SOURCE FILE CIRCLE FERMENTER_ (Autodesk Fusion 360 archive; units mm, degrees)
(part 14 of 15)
sketch "Schizzo16" plane through (0, 0, 68.1854) normal (0, 0, 1) x axis (-1, 0, 0)
  line L1 (6.7534, -5.4136) -> (35.6534, -5.4136)
  line L2 (6.7534, -27.4136) -> (6.7534, -5.4136)
  line L3 (79.5534, -27.4136) -> (6.7534, -27.4136)
  line L4 (79.5534, -5.4136) -> (79.5534, -27.4136)
  line L5 (50.6534, -5.4136) -> (79.5534, -5.4136)
  line L6 (50.6534, -6.4136) -> (50.6534, -5.4136)
  line L7 (36.6534, -7.4136) -> (49.6534, -7.4136)
  line L8 (35.6534, -5.4136) -> (35.6534, -6.4136)
  arc A1 centre (49.6534, -6.4136) radius 1 clockwise from (50.6534, -6.4136) to (49.6534, -7.4136)
  arc A2 centre (36.6534, -6.4136) radius 1 clockwise from (36.6534, -7.4136) to (35.6534, -6.4136)
  circle C1 centre (43.1534, -7.4136) radius 1
  point P14 (43.1534, -7.4136)
  midpoint L7 P14
  dimension "d98" diameter C1 = 2
extrude "Estrusione17" cut sketch "Schizzo16" profile of L7 C1 against normal blind 15.378
sketch "Schizzo18" plane through (0, 0, -22.6146) normal (0, 0, -1) x axis (1, 0, 0)
  line L1 (-79.5534, -5.4136) -> (-6.7534, -5.4136)
  line L2 (-79.5534, -27.4136) -> (-79.5534, -5.4136)
  line L3 (-6.7534, -27.4136) -> (-79.5534, -27.4136)
  line L4 (-6.7534, -5.4136) -> (-6.7534, -27.4136)
  line L5 (-43.1534, -27.4136) -> (-43.1534, -5.4136)
  line L6 (-40.1534, -7.4136) -> (-46.1534, -7.4136)
  line L7 (-46.1534, -3.4136) -> (-40.1534, -3.4136)
  line L8 (-40.1534, -5.4136) -> (-46.1534, -5.4136)
  arc A1 centre (-40.1534, -5.4136) radius 2 clockwise from (-40.1534, -3.4136) to (-40.1534, -7.4136)
  arc A2 centre (-46.1534, -5.4136) radius 2 clockwise from (-46.1534, -7.4136) to (-46.1534, -3.4136)
  point P6 (-43.1534, -5.4136)
  point P7 (-43.1534, -27.4136)
  point P14 (-43.1534, -5.4136)
  point P13 (-40.1534, -5.4136)
  midpoint L1 P6
  midpoint L3 P7
  tangent L6 A1
  tangent A1 L7
  parallel L6 L7
  tangent L7 A2
  tangent L6 A2
  perpendicular L5 L8
  coincident P6 P14
  midpoint L8 P14
  dimension "d101" diameter A1 = 4
  dimension "d104" distance P13 P14 = 3
extrude "Estrusione18" cut sketch "Schizzo18" profile of L1 L6 A1 L7 A2 against normal blind 17.359
sketch "Schizzo19" plane through (0, 5.4136, 0) normal (0, 1, 0) x axis (-1, 0, 0)
  line L1 (48.1534, -22.6146) -> (48.1534, -20.2146)
  line L2 (79.5534, -22.6146) -> (48.1534, -22.6146)
  line L3 (85.5534, 62.1854) -> (85.5534, -16.6146)
  line L4 (50.6534, 68.1854) -> (79.5534, 68.1854)
  line L5 (50.6534, 65.7854) -> (50.6534, 68.1854)
  line L6 (71.1534, 65.7854) -> (50.6534, 65.7854)
  line L7 (83.1534, -16.2146) -> (83.1534, 53.7854)
  line L8 (48.1534, -20.2146) -> (79.1534, -20.2146)
  line L9 (38.1534, -20.2146) -> (38.1534, -22.6146)
  line L10 (7.1534, -20.2146) -> (38.1534, -20.2146)
  line L11 (3.1534, 53.7854) -> (3.1534, -16.2146)
  line L12 (35.6534, 65.7854) -> (15.1534, 65.7854)
  line L13 (35.6534, 68.1854) -> (35.6534, 65.7854)
  line L14 (6.7534, 68.1854) -> (35.6534, 68.1854)
  line L15 (0.7534, -16.6146) -> (0.7534, 62.1854)
  line L16 (38.1534, -22.6146) -> (6.7534, -22.6146)
  line L17 (79.5534, -21.4146) -> (48.1534, -21.4146)
  line L18 (84.3534, 62.1854) -> (84.3534, -16.6146)
  line L19 (50.6534, 66.9854) -> (79.5534, 66.9854)
  line L20 (6.7534, 66.9854) -> (35.6534, 66.9854)
  line L21 (1.9534, -16.6146) -> (1.9534, 62.1854)
  line L22 (38.1534, -21.4146) -> (6.7534, -21.4146)
  arc A1 centre (79.5534, -16.6146) radius 6 clockwise from (85.5534, -16.6146) to (79.5534, -22.6146)
  arc A2 centre (79.5534, 62.1854) radius 6 clockwise from (79.5534, 68.1854) to (85.5534, 62.1854)
  arc A3 centre (71.1534, 61.7854) radius 4 clockwise from (71.1534, 65.7854) to (75.1534, 61.7854)
  arc A4 centre (79.1534, 61.7854) radius 4 clockwise from (79.1534, 57.7854) to (75.1534, 61.7854)
  arc A5 centre (79.1534, 53.7854) radius 4 clockwise from (79.1534, 57.7854) to (83.1534, 53.7854)
  arc A6 centre (79.1534, -16.2146) radius 4 clockwise from (83.1534, -16.2146) to (79.1534, -20.2146)
  circle C1 centre (79.1534, 61.7854) radius 1.875
  arc A7 centre (7.1534, -16.2146) radius 4 clockwise from (7.1534, -20.2146) to (3.1534, -16.2146)
  arc A8 centre (7.1534, 53.7854) radius 4 clockwise from (3.1534, 53.7854) to (7.1534, 57.7854)
  arc A9 centre (7.1534, 61.7854) radius 4 clockwise from (11.1534, 61.7854) to (7.1534, 57.7854)
  arc A10 centre (15.1534, 61.7854) radius 4 clockwise from (11.1534, 61.7854) to (15.1534, 65.7854)
  arc A11 centre (6.7534, 62.1854) radius 6 clockwise from (0.7534, 62.1854) to (6.7534, 68.1854)
  arc A12 centre (6.7534, -16.6146) radius 6 clockwise from (6.7534, -22.6146) to (0.7534, -16.6146)
  circle C2 centre (7.1534, 61.7854) radius 1.875
  arc A13 centre (79.5534, -16.6146) radius 4.8 clockwise from (84.3534, -16.6146) to (79.5534, -21.4146)
  arc A14 centre (79.5534, 62.1854) radius 4.8 clockwise from (79.5534, 66.9854) to (84.3534, 62.1854)
  arc A15 centre (6.7534, 62.1854) radius 4.8 clockwise from (1.9534, 62.1854) to (6.7534, 66.9854)
  arc A16 centre (6.7534, -16.6146) radius 4.8 clockwise from (6.7534, -21.4146) to (1.9534, -16.6146)
  dimension "d105" = -1.2
  dimension "d106" = -1.2
extrude "Estrusione19" cut sketch "Schizzo19" profile of L1 L2 A1 L3 A2 L4 L5 L9 L13 L14 A11 L15 A12 L16 A13 L17 L18 A14 L19 L20 L21 A15 A16 L22 against normal blind 1
extrude "Estrusione20" cut of existing geometry blind -13.899
sketch "Schizzo20" plane through (0, 5.4136, 0) normal (0, -1, 0) x axis (1, 0, 0)
  line L1 (-48.1534, -20.2146) -> (-48.1534, -22.6146)
  line L2 (-71.1534, -20.2146) -> (-48.1534, -20.2146)
  line L3 (-83.1534, 53.7854) -> (-83.1534, -8.2146)
  line L4 (-50.6534, 65.7854) -> (-71.1534, 65.7854)
  line L5 (-50.6534, 68.1854) -> (-50.6534, 65.7854)
  line L6 (-79.5534, 68.1854) -> (-50.6534, 68.1854)
  line L7 (-85.5534, -16.6146) -> (-85.5534, 62.1854)
  line L8 (-48.1534, -22.6146) -> (-79.5534, -22.6146)
  line L9 (-38.1534, -22.6146) -> (-38.1534, -20.2146)
  line L10 (-6.7534, -22.6146) -> (-38.1534, -22.6146)
  line L11 (-0.7534, 62.1854) -> (-0.7534, -16.6146)
  line L12 (-35.6534, 68.1854) -> (-6.7534, 68.1854)
  line L13 (-35.6534, 65.7854) -> (-35.6534, 68.1854)
  line L14 (-15.1534, 65.7854) -> (-35.6534, 65.7854)
  line L15 (-3.1534, -8.2146) -> (-3.1534, 53.7854)
  line L16 (-38.1534, -20.2146) -> (-15.1534, -20.2146)
  line L17 (-79.5534, 67.3854) -> (-50.6534, 67.3854)
  line L18 (-84.7534, -16.6146) -> (-84.7534, 62.1854)
  line L19 (-48.1534, -21.8146) -> (-79.5534, -21.8146)
  line L20 (-6.7534, -21.8146) -> (-38.1534, -21.8146)
  line L21 (-1.5534, 62.1854) -> (-1.5534, -16.6146)
  line L22 (-35.6534, 67.3854) -> (-6.7534, 67.3854)
  arc A1 centre (-71.1534, -16.2146) radius 4 clockwise from (-71.1534, -20.2146) to (-75.1534, -16.2146)
  arc A2 centre (-79.1534, -16.2146) radius 4 clockwise from (-79.1534, -12.2146) to (-75.1534, -16.2146)
  arc A3 centre (-79.1534, -8.2146) radius 4 clockwise from (-79.1534, -12.2146) to (-83.1534, -8.2146)
  arc A4 centre (-79.1534, 53.7854) radius 4 clockwise from (-83.1534, 53.7854) to (-79.1534, 57.7854)
  arc A5 centre (-79.1534, 61.7854) radius 4 clockwise from (-75.1534, 61.7854) to (-79.1534, 57.7854)
  arc A6 centre (-71.1534, 61.7854) radius 4 clockwise from (-75.1534, 61.7854) to (-71.1534, 65.7854)
  arc A7 centre (-79.5534, 62.1854) radius 6 clockwise from (-85.5534, 62.1854) to (-79.5534, 68.1854)
  arc A8 centre (-79.5534, -16.6146) radius 6 clockwise from (-79.5534, -22.6146) to (-85.5534, -16.6146)
  circle C1 centre (-79.1534, -16.2146) radius 1.725
  circle C2 centre (-79.1534, 61.7854) radius 1.875
  circle C3 centre (-7.1534, -16.2146) radius 1.725
  circle C4 centre (-7.1534, 61.7854) radius 1.875
  arc A9 centre (-6.7534, -16.6146) radius 6 clockwise from (-0.7534, -16.6146) to (-6.7534, -22.6146)
  arc A10 centre (-6.7534, 62.1854) radius 6 clockwise from (-6.7534, 68.1854) to (-0.7534, 62.1854)
  arc A11 centre (-15.1534, 61.7854) radius 4 clockwise from (-15.1534, 65.7854) to (-11.1534, 61.7854)
  arc A12 centre (-7.1534, 61.7854) radius 4 clockwise from (-7.1534, 57.7854) to (-11.1534, 61.7854)
  arc A13 centre (-7.1534, 53.7854) radius 4 clockwise from (-7.1534, 57.7854) to (-3.1534, 53.7854)
  arc A14 centre (-7.1534, -8.2146) radius 4 clockwise from (-3.1534, -8.2146) to (-7.1534, -12.2146)
  arc A15 centre (-7.1534, -16.2146) radius 4 clockwise from (-11.1534, -16.2146) to (-7.1534, -12.2146)
  arc A16 centre (-15.1534, -16.2146) radius 4 clockwise from (-11.1534, -16.2146) to (-15.1534, -20.2146)
  arc A17 centre (-79.5534, 62.1854) radius 5.2 clockwise from (-84.7534, 62.1854) to (-79.5534, 67.3854)
  arc A18 centre (-79.5534, -16.6146) radius 5.2 clockwise from (-79.5534, -21.8146) to (-84.7534, -16.6146)
  arc A19 centre (-6.7534, -16.6146) radius 5.2 clockwise from (-1.5534, -16.6146) to (-6.7534, -21.8146)
  arc A20 centre (-6.7534, 62.1854) radius 5.2 clockwise from (-6.7534, 67.3854) to (-1.5534, 62.1854)
  dimension "d111" = -0.8
  dimension "d112" = -0.8
extrude "Estrusione21" add sketch "Schizzo20" profile of L1 L5 L6 A7 L7 A8 L8 L9 L10 A9 L11 A10 L12 L13 L19 L17 A17 L18 A18 L20 A19 L21 A20 L22 along normal blind 0.8
thread "Filettatura"
sketch "Schizzo21" plane through (0, 5.4136, 0) normal (0, -1, 0) x axis (1, 0, 0)
  curve K1 (-6.1953, 60.9602) -> (-6.7549, 63.2761)
  curve K2 (-7.5519, 63.2761) -> (-8.1115, 60.9602)
  curve K3 (-8.1115, -15.3893) -> (-7.5519, -17.7052)
  curve K4 (-6.7549, -17.7052) -> (-6.1953, -15.3893)
  line L1 (-35.6534, 67.3854) -> (-6.7534, 67.3854)
  line L2 (-35.6534, 65.7854) -> (-35.6534, 67.3854)
  line L3 (-15.1534, 65.7854) -> (-35.6534, 65.7854)
  line L4 (-3.1534, -8.2146) -> (-3.1534, 53.7854)
  line L5 (-38.1534, -20.2146) -> (-15.1534, -20.2146)
  line L6 (-38.1534, -21.8146) -> (-38.1534, -20.2146)
  line L7 (-6.7534, -21.8146) -> (-38.1534, -21.8146)
  line L8 (-1.5534, 62.1854) -> (-1.5534, -16.6146)
  curve K5 (-78.1953, 60.9602) -> (-78.7549, 63.2761)
  curve K6 (-79.5519, 63.2761) -> (-80.1115, 60.9602)
  curve K7 (-80.1115, -15.3893) -> (-79.5519, -17.7052)
  curve K8 (-78.7549, -17.7052) -> (-78.1953, -15.3893)
  line L9 (-48.1534, -21.8146) -> (-79.5534, -21.8146)
  line L10 (-48.1534, -20.2146) -> (-48.1534, -21.8146)
  line L11 (-71.1534, -20.2146) -> (-48.1534, -20.2146)
  line L12 (-83.1534, 53.7854) -> (-83.1534, -8.2146)
  line L13 (-50.6534, 65.7854) -> (-71.1534, 65.7854)
  line L14 (-50.6534, 67.3854) -> (-50.6534, 65.7854)
  line L15 (-79.5534, 67.3854) -> (-50.6534, 67.3854)
  line L16 (-84.7534, -16.6146) -> (-84.7534, 62.1854)
  line L17 (-36.6534, 72.7854) -> (-36.6534, 62.7854)
  line L18 (-49.6534, 72.7854) -> (-36.6534, 72.7854)
  line L19 (-49.6534, 62.7854) -> (-49.6534, 72.7854)
  line L20 (-36.6534, 62.7854) -> (-49.6534, 62.7854)
  line L21 (-43.1534, 62.7854) -> (-43.1534, 72.7854)
  line L22 (-35.6534, 72.7854) -> (-36.6534, 72.7854)
  line L23 (-36.6534, 62.7854) -> (-36.6534, 72.7854)
  line L24 (-36.6534, 62.7854) -> (-35.6534, 62.7854)
  line L25 (-35.6534, 72.7854) -> (-35.6534, 62.7854)
  line L26 (-35.6534, 64.2854) -> (-30.6534, 65.7854)
  line L27 (-50.6534, 64.2854) -> (-55.6534, 65.7854)
  line L28 (-50.6534, 65.7854) -> (-50.6534, 64.2854)
  arc A1 centre (-7.1534, 61.7854) radius 1.2645 clockwise from (-6.1953, 60.9602) to (-8.1115, 60.9602)
  arc A2 centre (-7.1534, 61.7854) radius 1.543 clockwise from (-7.5519, 63.2761) to (-6.7549, 63.2761)
  arc A3 centre (-7.1534, -16.2146) radius 1.2645 clockwise from (-8.1115, -15.3893) to (-6.1953, -15.3893)
  arc A4 centre (-7.1534, -16.2146) radius 1.543 clockwise from (-6.7549, -17.7052) to (-7.5519, -17.7052)
  arc A5 centre (-15.1534, 61.7854) radius 4 clockwise from (-15.1534, 65.7854) to (-11.1534, 61.7854)
  arc A6 centre (-7.1534, 61.7854) radius 4 clockwise from (-7.1534, 57.7854) to (-11.1534, 61.7854)
  arc A7 centre (-7.1534, 53.7854) radius 4 clockwise from (-7.1534, 57.7854) to (-3.1534, 53.7854)
  arc A8 centre (-7.1534, -8.2146) radius 4 clockwise from (-3.1534, -8.2146) to (-7.1534, -12.2146)
  arc A9 centre (-7.1534, -16.2146) radius 4 clockwise from (-11.1534, -16.2146) to (-7.1534, -12.2146)
  arc A10 centre (-15.1534, -16.2146) radius 4 clockwise from (-11.1534, -16.2146) to (-15.1534, -20.2146)
  arc A11 centre (-6.7534, -16.6146) radius 5.2 clockwise from (-1.5534, -16.6146) to (-6.7534, -21.8146)
  arc A12 centre (-6.7534, 62.1854) radius 5.2 clockwise from (-6.7534, 67.3854) to (-1.5534, 62.1854)
  arc A13 centre (-79.1534, 61.7854) radius 1.2645 clockwise from (-78.1953, 60.9602) to (-80.1115, 60.9602)
  arc A14 centre (-79.1534, 61.7854) radius 1.543 clockwise from (-79.5519, 63.2761) to (-78.7549, 63.2761)
  arc A15 centre (-79.1534, -16.2146) radius 1.2645 clockwise from (-80.1115, -15.3893) to (-78.1953, -15.3893)
  arc A16 centre (-79.1534, -16.2146) radius 1.543 clockwise from (-78.7549, -17.7052) to (-79.5519, -17.7052)
  arc A17 centre (-71.1534, -16.2146) radius 4 clockwise from (-71.1534, -20.2146) to (-75.1534, -16.2146)
  arc A18 centre (-79.1534, -16.2146) radius 4 clockwise from (-79.1534, -12.2146) to (-75.1534, -16.2146)
  arc A19 centre (-79.1534, -8.2146) radius 4 clockwise from (-79.1534, -12.2146) to (-83.1534, -8.2146)
  arc A20 centre (-79.1534, 53.7854) radius 4 clockwise from (-83.1534, 53.7854) to (-79.1534, 57.7854)
  arc A21 centre (-79.1534, 61.7854) radius 4 clockwise from (-75.1534, 61.7854) to (-79.1534, 57.7854)
  arc A22 centre (-71.1534, 61.7854) radius 4 clockwise from (-75.1534, 61.7854) to (-71.1534, 65.7854)
  arc A23 centre (-79.5534, 62.1854) radius 5.2 clockwise from (-84.7534, 62.1854) to (-79.5534, 67.3854)
  arc A24 centre (-79.5534, -16.6146) radius 5.2 clockwise from (-79.5534, -21.8146) to (-84.7534, -16.6146)
  point P70 (-43.1534, 72.7854)
  point P71 (-43.1534, 62.7854)
  point P76 (-30.6534, 65.7854)
  point P77 (-35.6534, 64.2854)
  point P78 (-55.6534, 65.7854)
  point P79 (-50.6534, 64.2854)
  point P59 (-50.6534, 65.7854)
  point P80 (-50.6534, 65.7854)
  point P14 (-35.6534, 65.7854)
  midpoint L18 P70
  midpoint L20 P71
  coincident L3 P76
  coincident L25 P77
  symmetric L21 P76 P78
  symmetric L21 P77 P79
  coincident P59 P80
  dimension "d115" distance P14 P77 = 1.5
  dimension "d116" distance P14 P76 = 5
extrude "Estrusione22" add sketch "Schizzo21" profile of L3 L13 L25 L26 L27 L28 against normal blind 13.536
extrude "Estrusione23" cut of existing geometry blind -18.757
extrude "Estrusione24" add sketch "Schizzo21" profile of L3 L13 L25 L26 L27 L28 along normal blind 11
fillet "Raccordo6" radius 0.5 5
fillet "Raccordo7" radius 5 0.5
component_from_bodies "Corpo->Comp2"
component_from_bodies "Corpo->Comp3"
joint "Assembla5" alignAngle 90 alignOffsetX 0 alignOffsetY 0 alignOffsetZ 0
joint "Assembla6" alignAngle 0 alignOffsetX 0 alignOffsetY 0.2 alignOffsetZ 0
work_plane "Piano di lavoro1" AlongDistance -42.4 (= "( -84.8 / 2 ) * 1 mm")
work_plane "Piano di lavoro2" AlongDistance 20
work_plane "Piano di lavoro3" AlongDistance -20
remove_instance "RimuoviIstanza"
split "Dividi1"
split "Dividi2"
remove_body "RimuoviCorpo1"
remove_body "RimuoviCorpo2"
split "Dividi3"
remove_body "RimuoviCorpo3"
remove_body "RimuoviCorpo4"
move "Sposta1"
combine "Combina1"
work_plane "Piano di lavoro1" AlongDistance -10
work_plane "Piano di lavoro2" AlongDistance -30
split "Dividi1"
remove_body "RimuoviCorpo1"
split "Dividi2"
remove_body "RimuoviCorpo2"
move "Sposta1"
combine "Combina1"
mirror "Specchio" mirrorStitchTolerance 0.1
joint "Assembla7" alignAngle -90 alignOffsetX 0 alignOffsetY 0 alignOffsetZ 0
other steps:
base_feature "Lavorazione di base1"
base_feature "Lavorazione di base1"
joint_origin "OrigineGiunto1"
create_component "CreaComponente2"
remove_body "RimuoviCorpo2"
create_component "CreaComponente3"
remove_body "RimuoviCorpo3"
joint_origin "OrigineGiunto1"
joint_origin "OrigineGiunto1"
joint_origin "OrigineGiunto2"
create_component "CreaComponente4"
joint_origin "OrigineGiunto2"

design "rotary+encoder_14mm_hole_spc"
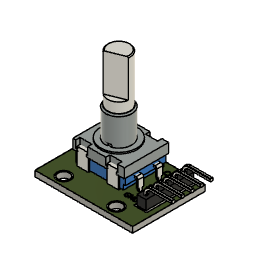
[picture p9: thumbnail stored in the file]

design "MODULO RISCALDATORE" references "PTC", "40x40x10 DC Fan"
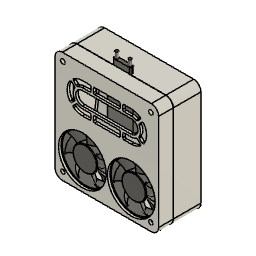
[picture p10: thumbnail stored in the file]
sketch "Schizzo1" plane through (0, 0, 0) normal (0, 1, 0) x axis (1, 0, 0)
  line L1 (40, -20) -> (-40, -20)
  line L2 (40, 20) -> (40, -20)
  line L3 (-40, 20) -> (40, 20)
  line L4 (-40, -20) -> (-40, 20)
  line L5 (40, 20) -> (-40, -20)
  line L6 (-40, 20) -> (40, -20)
  point P6 (0, 0)
  point P1 (0, 0)
  horizontal L1
  perpendicular L1 L2
  parallel L1 L3
  parallel L2 L4
  coincident L5 P6
  coincident L6 P6
  coincident P1 P6
  dimension "d1" distance L2 L4 = 80
  dimension "d2" distance L1 L3 = 40
component_insert "Inserimento componente1"
component_insert "Inserimento componente2"
joint "Assembla3" alignAngle 0 alignOffsetX 0 alignOffsetY 0 alignOffsetZ 0
sketch "Schizzo3" plane through (0, -5.5864, 0) normal (0, -1, 0) x axis (1, 0, 0)
  line L1 (-79.1534, 19.7854) -> (-47.1534, 19.7854)
  line L2 (-83.1534, -16.2146) -> (-83.1534, 15.7854)
  line L3 (-47.1534, -20.2146) -> (-79.1534, -20.2146)
  line L4 (-43.1534, 15.7854) -> (-43.1534, -16.2146)
  line L5 (-39.1534, 19.7854) -> (-7.1534, 19.7854)
  line L6 (-43.1534, -16.2146) -> (-43.1534, 15.7854)
  line L7 (-7.1534, -20.2146) -> (-39.1534, -20.2146)
  line L8 (-3.1534, 15.7854) -> (-3.1534, -16.2146)
  line L9 (-47.1534, 19.7854) -> (-39.1534, 19.7854)
  line L10 (-47.1534, -20.2146) -> (-39.1534, -20.2146)
  line L11 (-85.1534, -16.2146) -> (-85.1534, 15.7854)
  line L12 (-47.1534, -22.2146) -> (-79.1534, -22.2146)
  line L13 (-47.1534, -22.2146) -> (-39.1534, -22.2146)
  line L14 (-7.1534, -22.2146) -> (-39.1534, -22.2146)
  line L15 (-1.1534, 15.7854) -> (-1.1534, -16.2146)
  line L16 (-39.1534, 21.7854) -> (-7.1534, 21.7854)
  line L17 (-47.1534, 21.7854) -> (-39.1534, 21.7854)
  line L18 (-79.1534, 21.7854) -> (-47.1534, 21.7854)
  line L19 (-1.1534, 67.7854) -> (-1.1534, 15.7854)
  line L20 (-85.1534, 67.7854) -> (-1.1534, 67.7854)
  line L21 (-85.1534, 15.7854) -> (-85.1534, 67.7854)
  arc A1 centre (-47.1534, 15.7854) radius 4 clockwise from (-47.1534, 19.7854) to (-43.1534, 15.7854)
  arc A2 centre (-79.1534, 15.7854) radius 4 clockwise from (-83.1534, 15.7854) to (-79.1534, 19.7854)
  arc A3 centre (-79.1534, -16.2146) radius 4 clockwise from (-79.1534, -20.2146) to (-83.1534, -16.2146)
  arc A4 centre (-47.1534, -16.2146) radius 4 clockwise from (-43.1534, -16.2146) to (-47.1534, -20.2146)
  circle C1 centre (-79.1534, 15.7854) radius 1.725
  circle C2 centre (-79.1534, -16.2146) radius 1.725
  circle C3 centre (-47.1534, -16.2146) radius 1.725
  circle C4 centre (-47.1534, 15.7854) radius 1.725
  circle C5 centre (-63.1534, -0.2146) radius 19.5
  arc A5 centre (-7.1534, 15.7854) radius 4 clockwise from (-7.1534, 19.7854) to (-3.1534, 15.7854)
  arc A6 centre (-39.1534, 15.7854) radius 4 clockwise from (-43.1534, 15.7854) to (-39.1534, 19.7854)
  arc A7 centre (-39.1534, -16.2146) radius 4 clockwise from (-39.1534, -20.2146) to (-43.1534, -16.2146)
  arc A8 centre (-7.1534, -16.2146) radius 4 clockwise from (-3.1534, -16.2146) to (-7.1534, -20.2146)
  circle C6 centre (-39.1534, 15.7854) radius 1.725
  circle C7 centre (-39.1534, -16.2146) radius 1.725
  circle C8 centre (-7.1534, -16.2146) radius 1.725
  circle C9 centre (-7.1534, 15.7854) radius 1.725
  circle C10 centre (-23.1534, -0.2146) radius 19.5
  arc A9 centre (-79.1534, -16.2146) radius 6 clockwise from (-79.1534, -22.2146) to (-85.1534, -16.2146)
  arc A10 centre (-7.1534, -16.2146) radius 6 clockwise from (-1.1534, -16.2146) to (-7.1534, -22.2146)
  point P18 (-39.1534, 19.7854)
  point P28 (-39.1534, 19.7854)
  point P3 (-47.1534, 19.7854)
  point P29 (-47.1534, 19.7854)
  point P22 (-39.1534, -20.2146)
  point P30 (-39.1534, -20.2146)
  point P11 (-47.1534, -20.2146)
  point P31 (-47.1534, -20.2146)
  coincident P18 P28
  coincident P3 P29
  coincident P22 P30
  coincident P11 P31
  concentric A3 A9
  concentric A8 A10
  tangent A9 L12
  tangent L11 A9
  tangent L14 A10
  tangent A10 L15
  parallel L15 L19
  perpendicular L19 L20
  vertical L21
  dimension "d32" distance L12 L20 = 90
extrude "Estrusione2" new body sketch "Schizzo3" profile of A1 L1 A2 L2 A3 L3 A4 L4 C1 C2 C3 C4 C5 A5 L5 A6 L6 A7 L7 A8 L8 C6 C7 C8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 along normal blind 2
fillet "Raccordo1" radius 6
sketch "Schizzo4" plane through (0, -5.5864, 0) normal (0, 1, 0) x axis (-1, 0, 0)
  line L1 (1.1534, -16.2146) -> (1.1534, 61.7854)
  line L2 (79.1534, -22.2146) -> (7.1534, -22.2146)
  line L3 (85.1534, 61.7854) -> (85.1534, -16.2146)
  line L4 (7.1534, 67.7854) -> (79.1534, 67.7854)
  line L5 (7.1534, 65.7854) -> (79.1534, 65.7854)
  line L6 (3.1534, -16.2146) -> (3.1534, 61.7854)
  line L7 (79.1534, -20.2146) -> (7.1534, -20.2146)
  line L8 (83.1534, 61.7854) -> (83.1534, -16.2146)
  circle C1 centre (7.1534, -16.2146) radius 1.725
  circle C2 centre (23.1534, -0.2146) radius 19.5
  circle C3 centre (63.1534, -0.2146) radius 19.5
  circle C4 centre (79.1534, -16.2146) radius 1.725
  arc A1 centre (7.1534, 61.7854) radius 6 clockwise from (1.1534, 61.7854) to (7.1534, 67.7854)
  arc A2 centre (7.1534, -16.2146) radius 6 clockwise from (7.1534, -22.2146) to (1.1534, -16.2146)
  arc A3 centre (79.1534, -16.2146) radius 6 clockwise from (85.1534, -16.2146) to (79.1534, -22.2146)
  arc A4 centre (79.1534, 61.7854) radius 6 clockwise from (79.1534, 67.7854) to (85.1534, 61.7854)
  arc A5 centre (7.1534, 61.7854) radius 4 clockwise from (3.1534, 61.7854) to (7.1534, 65.7854)
  arc A6 centre (7.1534, -16.2146) radius 4 clockwise from (7.1534, -20.2146) to (3.1534, -16.2146)
  arc A7 centre (79.1534, -16.2146) radius 4 clockwise from (83.1534, -16.2146) to (79.1534, -20.2146)
  arc A8 centre (79.1534, 61.7854) radius 4 clockwise from (79.1534, 65.7854) to (83.1534, 61.7854)
  dimension "d37" = -2
extrude "Estrusione3" add sketch "Schizzo4" profile of A1 L1 A2 L2 A3 L3 A4 L4 L5 A8 L7 A5 L6 A6 L8 A7 along normal blind 25
component_insert "Inserimento componente3"
joint "Assembla4" alignAngle 180 alignOffsetX 0 alignOffsetY 0 alignOffsetZ 5
sketch "Schizzo5" plane through (0, -5.5864, 0) normal (0, 1, 0) x axis (-1, 0, 0)
  line L1 (7.1534, 65.7854) -> (79.1534, 65.7854)
  line L2 (3.1534, -16.2146) -> (3.1534, 61.7854)
  line L3 (79.1534, -20.2146) -> (7.1534, -20.2146)
  line L4 (83.1534, 61.7854) -> (83.1534, -16.2146)
  line L5 (47.1534, 19.7854) -> (79.1534, 19.7854)
  line L6 (7.1534, 19.7854) -> (39.1534, 19.7854)
  arc A1 centre (7.1534, 61.7854) radius 4 clockwise from (3.1534, 61.7854) to (7.1534, 65.7854)
  arc A2 centre (7.1534, -16.2146) radius 4 clockwise from (7.1534, -20.2146) to (3.1534, -16.2146)
  arc A3 centre (79.1534, -16.2146) radius 4 clockwise from (83.1534, -16.2146) to (79.1534, -20.2146)
  arc A4 centre (79.1534, 61.7854) radius 4 clockwise from (79.1534, 65.7854) to (83.1534, 61.7854)
  circle C1 centre (7.1534, -16.2146) radius 1.725
  circle C2 centre (63.1534, -0.2146) radius 19.5
  circle C3 centre (79.1534, -16.2146) radius 1.725
  circle C4 centre (23.1534, -0.2146) radius 19.5
sketch "Schizzo6" plane through (0, 0, 67.7854) normal (0, 0, 1) x axis (-1, 0, 0)
  line L1 (7.1534, -19.4136) -> (7.1534, 7.5864)
  line L2 (79.1534, -19.4136) -> (7.1534, -19.4136)
  line L3 (79.1534, 7.5864) -> (79.1534, -19.4136)
  line L4 (7.1534, 7.5864) -> (79.1534, 7.5864)
  line L5 (49.6534, -7.4136) -> (36.6534, -7.4136)
  line L6 (50.6534, -5.4136) -> (50.6534, -6.4136)
  line L7 (36.6534, -4.4136) -> (49.6534, -4.4136)
  line L8 (35.6534, -6.4136) -> (35.6534, -5.4136)
  line L9 (50.6534, -19.4136) -> (50.6534, -6.4136)
  line L10 (35.6534, -19.4136) -> (35.6534, -6.4136)
  circle C1 centre (48.6534, -5.9136) radius 1.25
  circle C2 centre (37.6534, -5.9136) radius 1.25
  arc A1 centre (36.6534, -6.4136) radius 1 clockwise from (36.6534, -7.4136) to (35.6534, -6.4136)
  arc A2 centre (49.6534, -6.4136) radius 1 clockwise from (50.6534, -6.4136) to (49.6534, -7.4136)
  arc A3 centre (49.6534, -5.4136) radius 1 clockwise from (49.6534, -4.4136) to (50.6534, -5.4136)
  arc A4 centre (36.6534, -5.4136) radius 1 clockwise from (35.6534, -5.4136) to (36.6534, -4.4136)
  point P12 (50.6534, -6.4136)
  point P20 (50.6534, -6.4136)
  point P21 (50.6534, -19.4136)
  point P8 (35.6534, -6.4136)
  point P22 (35.6534, -6.4136)
  point P23 (35.6534, -19.4136)
  coincident P12 P20
  coincident L2 P21
  tangent A2 L9
  coincident P8 P22
  coincident L2 P23
  tangent A1 L10
extrude "Estrusione4" cut sketch "Schizzo6" profile of L2 C1 C2 A1 L5 A2 L6 A3 L7 A4 L8 L9 L10 against normal blind 5.599
extrude "Estrusione5" cut of existing geometry blind -14
sketch "Schizzo7" plane through (0, -7.5864, 0) normal (0, -1, 0) x axis (1, 0, 0)
  line L1 (-79.1534, 67.7854) -> (-7.1534, 67.7854)
  line L2 (-85.1534, -16.2146) -> (-85.1534, 61.7854)
  line L3 (-7.1534, -22.2146) -> (-79.1534, -22.2146)
  line L4 (-1.1534, 61.7854) -> (-1.1534, -16.2146)
  line L5 (-43.1534, -22.2146) -> (-43.1534, 67.7854)
  line L6 (-23.1534, 31.2854) -> (-63.1534, 31.2854)
  line L7 (-63.1534, 56.2854) -> (-23.1534, 56.2854)
  line L8 (-23.1534, 43.7854) -> (-63.1534, 43.7854)
  arc A1 centre (-7.1534, 61.7854) radius 6 clockwise from (-7.1534, 67.7854) to (-1.1534, 61.7854)
  arc A2 centre (-79.1534, 61.7854) radius 6 clockwise from (-85.1534, 61.7854) to (-79.1534, 67.7854)
  arc A3 centre (-79.1534, -16.2146) radius 6 clockwise from (-79.1534, -22.2146) to (-85.1534, -16.2146)
  arc A4 centre (-7.1534, -16.2146) radius 6 clockwise from (-1.1534, -16.2146) to (-7.1534, -22.2146)
  circle C1 centre (-7.1534, -16.2146) radius 1.725
  circle C2 centre (-63.1534, -0.2146) radius 19.5
  circle C3 centre (-79.1534, -16.2146) radius 1.725
  circle C4 centre (-23.1534, -0.2146) radius 19.5
  arc A5 centre (-23.1534, 43.7854) radius 12.5 clockwise from (-23.1534, 56.2854) to (-23.1534, 31.2854)
  arc A6 centre (-63.1534, 43.7854) radius 12.5 clockwise from (-63.1534, 31.2854) to (-63.1534, 56.2854)
  point P16 (-43.1534, 67.7854)
  point P17 (-43.1534, -22.2146)
  point P24 (-43.1534, 43.7854)
  point P23 (-23.1534, 43.7854)
  midpoint L1 P16
  midpoint L3 P17
  tangent L6 A5
  tangent A5 L7
  parallel L6 L7
  tangent L7 A6
  tangent L6 A6
  perpendicular L5 L8
  coincident L5 P24
  midpoint L8 P24
  dimension "d48" distance L6 L7 = 25
  dimension "d49" distance L5 P23 = 20
  dimension "d50" distance L1 P24 = 24
extrude "Estrusione6" cut sketch "Schizzo7" profile of L6 A5 L7 A6 against normal blind 2
sketch "Schizzo8" plane through (0, -7.5864, 0) normal (0, -1, 0) x axis (1, 0, 0)
  line L1 (-63.1534, 31.2854) -> (-23.1534, 31.2854)
  line L2 (-23.1534, 56.2854) -> (-63.1534, 56.2854)
  line L3 (-79.1534, 67.7854) -> (-7.1534, 67.7854)
  line L4 (-85.1534, -16.2146) -> (-85.1534, 61.7854)
  line L5 (-7.1534, -22.2146) -> (-79.1534, -22.2146)
  line L6 (-1.1534, 61.7854) -> (-1.1534, -16.2146)
  line L7 (-23.1534, 51.2854) -> (-63.1534, 51.2854)
  line L8 (-63.1534, 36.2854) -> (-23.1534, 36.2854)
  line L9 (-23.1534, 49.2854) -> (-63.1534, 49.2854)
  line L10 (-63.1534, 38.2854) -> (-23.1534, 38.2854)
  line L11 (-43.1534, 56.2854) -> (-43.1534, 51.2854)
  line L12 (-42.1534, 56.2854) -> (-42.1534, 51.2854)
  line L13 (-44.1534, 56.2854) -> (-44.1534, 51.2854)
  line L14 (-63.1534, 43.7854) -> (-23.1534, 43.7854)
  line L15 (-71.9922, 52.6243) -> (-63.1534, 43.7854)
  line L16 (-50.6534, 43.7854) -> (-63.1534, 43.7854)
  line L17 (-71.2568, 53.3031) -> (-67.7022, 49.7485)
  line L18 (-72.671, 51.8888) -> (-69.1164, 48.3343)
  line L19 (-54.1534, 51.2854) -> (-56.1534, 51.2854)
  line L20 (-54.1534, 56.2854) -> (-54.1534, 51.2854)
  line L21 (-56.1534, 56.2854) -> (-54.1534, 56.2854)
  line L22 (-56.1534, 51.2854) -> (-56.1534, 56.2854)
  line L23 (-15.05, 53.3031) -> (-18.6045, 49.7485)
  line L24 (-13.6358, 51.8888) -> (-17.1903, 48.3343)
  line L25 (-30.1534, 51.2854) -> (-30.1534, 56.2854)
  line L26 (-32.1534, 56.2854) -> (-32.1534, 51.2854)
  line L27 (-44.1534, 31.2854) -> (-44.1534, 36.2854)
  line L28 (-42.1534, 31.2854) -> (-42.1534, 36.2854)
  line L29 (-32.1534, 31.2854) -> (-32.1534, 36.2854)
  line L30 (-30.1534, 36.2854) -> (-30.1534, 31.2854)
  line L31 (-15.05, 34.2678) -> (-18.6045, 37.8224)
  line L32 (-13.6358, 35.682) -> (-17.1903, 39.2366)
  line L33 (-54.1534, 31.2854) -> (-54.1534, 36.2854)
  line L34 (-56.1534, 36.2854) -> (-56.1534, 31.2854)
  line L35 (-71.2568, 34.2678) -> (-67.7022, 37.8224)
  line L36 (-72.671, 35.682) -> (-69.1164, 39.2366)
  arc A1 centre (-63.1534, 43.7854) radius 12.5 clockwise from (-63.1534, 31.2854) to (-63.1534, 56.2854)
  arc A2 centre (-23.1534, 43.7854) radius 12.5 clockwise from (-23.1534, 56.2854) to (-23.1534, 31.2854)
  arc A3 centre (-7.1534, 61.7854) radius 6 clockwise from (-7.1534, 67.7854) to (-1.1534, 61.7854)
  arc A4 centre (-79.1534, 61.7854) radius 6 clockwise from (-85.1534, 61.7854) to (-79.1534, 67.7854)
  arc A5 centre (-79.1534, -16.2146) radius 6 clockwise from (-79.1534, -22.2146) to (-85.1534, -16.2146)
  arc A6 centre (-7.1534, -16.2146) radius 6 clockwise from (-1.1534, -16.2146) to (-7.1534, -22.2146)
  circle C1 centre (-7.1534, -16.2146) radius 1.725
  circle C2 centre (-63.1534, -0.2146) radius 19.5
  circle C3 centre (-79.1534, -16.2146) radius 1.725
  circle C4 centre (-23.1534, -0.2146) radius 19.5
  arc A7 centre (-23.1534, 43.7854) radius 7.5 clockwise from (-23.1534, 51.2854) to (-23.1534, 36.2854)
  arc A8 centre (-63.1534, 43.7854) radius 7.5 clockwise from (-63.1534, 36.2854) to (-63.1534, 51.2854)
  arc A9 centre (-23.1534, 43.7854) radius 5.5 clockwise from (-23.1534, 49.2854) to (-23.1534, 38.2854)
  arc A10 centre (-63.1534, 43.7854) radius 5.5 clockwise from (-63.1534, 38.2854) to (-63.1534, 49.2854)
  point P34 (-43.1534, 51.2854)
  point P35 (-43.1534, 56.2854)
  point P36 (-42.1534, 51.2854)
  point P37 (-42.1534, 56.2854)
  point P38 (-44.1534, 51.2854)
  point P39 (-44.1534, 56.2854)
  point P7 (-23.1534, 43.7854)
  point P40 (-23.1534, 43.7854)
  point P5 (-63.1534, 43.7854)
  point P41 (-63.1534, 43.7854)
  point P42 (-63.1534, 43.7854)
  point P45 (-67.7022, 49.7485)
  point P46 (-71.2568, 53.3031)
  point P47 (-69.1164, 48.3343)
  point P48 (-72.671, 51.8888)
  point P51 (-54.1534, 56.2854)
  point P49 (-56.1534, 51.2854)
  point P53 (-18.6045, 49.7485)
  point P54 (-15.05, 53.3031)
  point P55 (-17.1903, 48.3343)
  point P56 (-13.6358, 51.8888)
  point P58 (-30.1534, 51.2854)
  point P50 (-54.1534, 51.2854)
  point P59 (-32.1534, 51.2854)
  point P60 (-32.1534, 56.2854)
  point P52 (-56.1534, 56.2854)
  point P57 (-30.1534, 56.2854)
  point P63 (-42.1534, 36.2854)
  point P64 (-42.1534, 31.2854)
  point P61 (-44.1534, 36.2854)
  point P62 (-44.1534, 31.2854)
  point P77 (-67.7022, 37.8224)
  point P78 (-71.2568, 34.2678)
  point P79 (-69.1164, 39.2366)
  point P80 (-72.671, 35.682)
  point P76 (-56.1534, 36.2854)
  point P73 (-54.1534, 36.2854)
  point P74 (-54.1534, 31.2854)
  point P75 (-56.1534, 31.2854)
  point P69 (-18.6045, 37.8224)
  point P70 (-15.05, 34.2678)
  point P71 (-17.1903, 39.2366)
  point P72 (-13.6358, 35.682)
  point P67 (-30.1534, 31.2854)
  point P68 (-30.1534, 36.2854)
  point P65 (-32.1534, 36.2854)
  point P66 (-32.1534, 31.2854)
  midpoint L7 P34
  midpoint L2 P35
  perpendicular L2 L11
  coincident L7 P36
  coincident L2 P37
  perpendicular L2 L12
  coincident L7 P38
  coincident L2 P39
  perpendicular L2 L13
  coincident P7 P40
  coincident P5 P41
  horizontal L16
  coincident P5 P42
  coincident A8 P45
  coincident A1 P46
  coincident A8 P47
  coincident A1 P48
  parallel L15 L18
  parallel L15 L17
  horizontal L19
  vertical L20
  horizontal L21
  vertical L22
  coincident L2 P51
  coincident L7 P49
  symmetric L11 P45 P53
  symmetric L11 P46 P54
  symmetric L11 P47 P55
  symmetric L11 P48 P56
  symmetric L11 P49 P58
  symmetric L11 P50 P59
  symmetric L11 P51 P60
  symmetric L11 P52 P57
  symmetric P36 L14 P63
  symmetric P37 L14 P64
  symmetric P38 L14 P61
  symmetric P39 L14 P62
  symmetric L14 P45 P77
  symmetric L14 P46 P78
  symmetric L14 P47 P79
  symmetric L14 P48 P80
  symmetric L14 P49 P76
  symmetric L14 P50 P73
  symmetric L14 P51 P74
  symmetric L14 P52 P75
  symmetric L14 P53 P69
  symmetric L14 P54 P70
  symmetric L14 P55 P71
  symmetric L14 P56 P72
  symmetric L14 P57 P67
  symmetric L14 P58 P68
  symmetric L14 P59 P65
  symmetric L14 P60 P66
  dimension "d53" = -5
  dimension "d54" = -7
  dimension "d55" distance L11 L13 = 1
  dimension "d56" distance L11 L12 = 1 (= "d55")
  dimension "d57" angle L15 L16 = 135
  dimension "d58" distance L17 L18 = 2
  dimension "d59" distance L15 L17 = 1
  dimension "d60" distance L20 L22 = 2
  dimension "d61" distance L12 L20 = 12
extrude "Estrusione7" add sketch "Schizzo8" profile of L1 A1 L2 A2 L7 A7 L8 A8 L9 A9 L10 A10 L17 L18 L19 L20 L21 L22 L23 L24 L25 L26 L29 L30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 against normal blind 2
fillet "Raccordo2" radius 1
offset_faces "FacceDiOffset" distance 0.4
sketch "Schizzo9" plane through (0, -5.5864, 0) normal (0, 1, 0) x axis (-1, 0, 0)
  line L1 (57.1534, 31.2854) -> (63.1534, 31.2854)
  curve K1 (57.1534, 31.2854) -> (56.1534, 32.2854)
  line L2 (56.1534, 35.2854) -> (56.1534, 32.2854)
  curve K2 (56.1534, 35.2854) -> (57.1534, 36.2854)
  line L3 (63.1534, 36.2854) -> (57.1534, 36.2854)
  curve K3 (67.0599, 37.3832) -> (68.2879, 37.2367)
  line L4 (70.4541, 35.0705) -> (68.2879, 37.2367)
  curve K4 (70.4541, 35.0705) -> (70.3203, 33.5441)
  line L5 (33.1534, 31.2854) -> (53.1534, 31.2854)
  curve K5 (33.1534, 31.2854) -> (32.1534, 32.2854)
  line L6 (32.1534, 35.2854) -> (32.1534, 32.2854)
  curve K6 (32.1534, 35.2854) -> (33.1534, 36.2854)
  line L7 (53.1534, 36.2854) -> (33.1534, 36.2854)
  curve K7 (53.1534, 36.2854) -> (54.1534, 35.2854)
  line L8 (54.1534, 32.2854) -> (54.1534, 35.2854)
  curve K8 (54.1534, 32.2854) -> (53.1534, 31.2854)
  line L9 (23.1534, 31.2854) -> (29.1534, 31.2854)
  curve K9 (15.9864, 33.5441) -> (15.8527, 35.0705)
  line L10 (18.0188, 37.2367) -> (15.8527, 35.0705)
  curve K10 (18.0188, 37.2367) -> (19.2468, 37.3832)
  line L11 (29.1534, 36.2854) -> (23.1534, 36.2854)
  curve K11 (29.1534, 36.2854) -> (30.1534, 35.2854)
  line L12 (30.1534, 32.2854) -> (30.1534, 35.2854)
  curve K12 (30.1534, 32.2854) -> (29.1534, 31.2854)
  curve K13 (12.912, 50.9524) -> (14.4385, 51.0862)
  line L13 (16.6046, 48.92) -> (14.4385, 51.0862)
  curve K14 (16.6046, 48.92) -> (16.7511, 47.692)
  curve K15 (16.7511, 39.8789) -> (16.6046, 38.6509)
  line L14 (14.4385, 36.4847) -> (16.6046, 38.6509)
  curve K16 (14.4385, 36.4847) -> (12.912, 36.6185)
  line L15 (29.1534, 56.2854) -> (23.1534, 56.2854)
  curve K17 (29.1534, 56.2854) -> (30.1534, 55.2854)
  line L16 (30.1534, 52.2854) -> (30.1534, 55.2854)
  curve K18 (30.1534, 52.2854) -> (29.1534, 51.2854)
  line L17 (23.1534, 51.2854) -> (29.1534, 51.2854)
  curve K19 (19.2468, 50.1877) -> (18.0188, 50.3342)
  line L18 (15.8527, 52.5004) -> (18.0188, 50.3342)
  curve K20 (15.8527, 52.5004) -> (15.9864, 54.0268)
  line L19 (53.1534, 56.2854) -> (33.1534, 56.2854)
  curve K21 (53.1534, 56.2854) -> (54.1534, 55.2854)
  line L20 (54.1534, 52.2854) -> (54.1534, 55.2854)
  curve K22 (54.1534, 52.2854) -> (53.1534, 51.2854)
  line L21 (33.1534, 51.2854) -> (53.1534, 51.2854)
  curve K23 (33.1534, 51.2854) -> (32.1534, 52.2854)
  line L22 (32.1534, 55.2854) -> (32.1534, 52.2854)
  curve K24 (32.1534, 55.2854) -> (33.1534, 56.2854)
  line L23 (63.1534, 56.2854) -> (57.1534, 56.2854)
  curve K25 (70.3203, 54.0268) -> (70.4541, 52.5004)
  line L24 (68.2879, 50.3342) -> (70.4541, 52.5004)
  curve K26 (68.2879, 50.3342) -> (67.0599, 50.1877)
  line L25 (57.1534, 51.2854) -> (63.1534, 51.2854)
  curve K27 (57.1534, 51.2854) -> (56.1534, 52.2854)
  line L26 (56.1534, 55.2854) -> (56.1534, 52.2854)
  curve K28 (56.1534, 55.2854) -> (57.1534, 56.2854)
  line L27 (63.1534, 49.2854) -> (23.1534, 49.2854)
  line L28 (23.1534, 38.2854) -> (63.1534, 38.2854)
  line L29 (69.7021, 38.6509) -> (71.8683, 36.4847)
  curve K29 (69.7021, 38.6509) -> (69.5556, 39.8789)
  curve K30 (69.5556, 47.692) -> (69.7021, 48.92)
  line L30 (71.8683, 51.0862) -> (69.7021, 48.92)
  curve K31 (71.8683, 51.0862) -> (73.3947, 50.9524)
  curve K32 (73.3947, 36.6185) -> (71.8683, 36.4847)
  line L31 (7.1534, 65.7854) -> (79.1534, 65.7854)
  line L32 (3.1534, -16.2146) -> (3.1534, 61.7854)
  line L33 (79.1534, -20.2146) -> (7.1534, -20.2146)
  line L34 (83.1534, 61.7854) -> (83.1534, -16.2146)
  line L35 (3.1534, 22.7854) -> (83.1534, 22.7854)
  arc A1 centre (63.1534, 43.7854) radius 12.5 clockwise from (70.3203, 33.5441) to (63.1534, 31.2854)
  arc A2 centre (63.1534, 43.7854) radius 7.5 clockwise from (67.0599, 37.3832) to (63.1534, 36.2854)
  arc A3 centre (23.1534, 43.7854) radius 12.5 clockwise from (23.1534, 31.2854) to (15.9864, 33.5441)
  arc A4 centre (23.1534, 43.7854) radius 7.5 clockwise from (23.1534, 36.2854) to (19.2468, 37.3832)
  arc A5 centre (23.1534, 43.7854) radius 12.5 clockwise from (12.912, 36.6185) to (12.912, 50.9524)
  arc A6 centre (23.1534, 43.7854) radius 7.5 clockwise from (16.7511, 39.8789) to (16.7511, 47.692)
  arc A7 centre (23.1534, 43.7854) radius 12.5 clockwise from (15.9864, 54.0268) to (23.1534, 56.2854)
  arc A8 centre (23.1534, 43.7854) radius 7.5 clockwise from (19.2468, 50.1877) to (23.1534, 51.2854)
  arc A9 centre (63.1534, 43.7854) radius 12.5 clockwise from (63.1534, 56.2854) to (70.3203, 54.0268)
  arc A10 centre (63.1534, 43.7854) radius 7.5 clockwise from (63.1534, 51.2854) to (67.0599, 50.1877)
  arc A11 centre (23.1534, 43.7854) radius 5.5 clockwise from (23.1534, 38.2854) to (23.1534, 49.2854)
  arc A12 centre (63.1534, 43.7854) radius 5.5 clockwise from (63.1534, 49.2854) to (63.1534, 38.2854)
  arc A13 centre (63.1534, 43.7854) radius 7.5 clockwise from (69.5556, 47.692) to (69.5556, 39.8789)
  arc A14 centre (63.1534, 43.7854) radius 12.5 clockwise from (73.3947, 50.9524) to (73.3947, 36.6185)
  arc A15 centre (7.1534, 61.7854) radius 4 clockwise from (3.1534, 61.7854) to (7.1534, 65.7854)
  arc A16 centre (7.1534, -16.2146) radius 4 clockwise from (7.1534, -20.2146) to (3.1534, -16.2146)
  arc A17 centre (79.1534, -16.2146) radius 4 clockwise from (83.1534, -16.2146) to (79.1534, -20.2146)
  arc A18 centre (79.1534, 61.7854) radius 4 clockwise from (79.1534, 65.7854) to (83.1534, 61.7854)
  circle C1 centre (7.1534, -16.2146) radius 1.725
  circle C2 centre (63.1534, -0.2146) radius 19.5
  circle C3 centre (79.1534, -16.2146) radius 1.725
  circle C4 centre (23.1534, -0.2146) radius 19.5
  circle C5 centre (7.1534, -16.2146) radius 1.725
  circle C6 centre (79.1534, -16.2146) radius 1.725
  circle C7 centre (79.1534, 61.7854) radius 1.725
  circle C8 centre (7.1534, 61.7854) radius 1.875
  circle C9 centre (79.1534, 61.7854) radius 1.875
  circle C10 centre (79.1534, 61.7854) radius 4
  circle C11 centre (7.1534, 61.7854) radius 4
  point P96 (83.1534, 22.7854)
  point P97 (3.1534, 22.7854)
  point P94 (7.1534, -16.2146)
  point P98 (7.1534, 61.7854)
  midpoint L34 P96
  midpoint L32 P97
  symmetric C3 L35 C7
  symmetric P94 L35 P98
  concentric A15 C8
  concentric A18 C9
  concentric A18 C10
  concentric A15 C11
  dimension "d67" diameter C8 = 3.75
  dimension "d68" diameter C9 = 3.75
  dimension "d69" diameter C11 = 8
  dimension "d70" diameter C10 = 8
extrude "Estrusione8" add sketch "Schizzo9" profile of A15 A18 C8 C9 C10 C11 along normal blind 11
fillet "Raccordo3" radius 4
extrude "Estrusione9" new body of existing geometry blind 20
sketch "Schizzo10" plane through (0, 25.4136, 0) normal (0, 1, 0) x axis (-1, 0, 0)
  line L1 (85.5534, 62.1854) -> (85.5534, -16.6146)
  line L2 (50.6534, 68.1854) -> (79.5534, 68.1854)
  line L3 (50.6534, 65.7854) -> (50.6534, 68.1854)
  line L4 (71.1534, 65.7854) -> (50.6534, 65.7854)
  line L5 (83.1534, -16.2146) -> (83.1534, 53.7854)
  line L6 (7.1534, -20.2146) -> (79.1534, -20.2146)
  line L7 (3.1534, 53.7854) -> (3.1534, -16.2146)
  line L8 (35.6534, 65.7854) -> (15.1534, 65.7854)
  line L9 (35.6534, 68.1854) -> (35.6534, 65.7854)
  line L10 (6.7534, 68.1854) -> (35.6534, 68.1854)
  line L11 (0.7534, -16.6146) -> (0.7534, 62.1854)
  line L12 (79.5534, -22.6146) -> (6.7534, -22.6146)
  line L13 (0.7534, 22.7854) -> (85.5534, 22.7854)
  circle C1 centre (79.1534, 61.7854) radius 1.875
  circle C2 centre (7.1534, 61.7854) radius 1.875
  arc A1 centre (79.5534, -16.6146) radius 6 clockwise from (85.5534, -16.6146) to (79.5534, -22.6146)
  arc A2 centre (79.5534, 62.1854) radius 6 clockwise from (79.5534, 68.1854) to (85.5534, 62.1854)
  arc A3 centre (71.1534, 61.7854) radius 4 clockwise from (71.1534, 65.7854) to (75.1534, 61.7854)
  arc A4 centre (79.1534, 61.7854) radius 4 clockwise from (79.1534, 57.7854) to (75.1534, 61.7854)
  arc A5 centre (79.1534, 53.7854) radius 4 clockwise from (79.1534, 57.7854) to (83.1534, 53.7854)
  arc A6 centre (79.1534, -16.2146) radius 4 clockwise from (83.1534, -16.2146) to (79.1534, -20.2146)
  arc A7 centre (7.1534, -16.2146) radius 4 clockwise from (7.1534, -20.2146) to (3.1534, -16.2146)
  arc A8 centre (7.1534, 53.7854) radius 4 clockwise from (3.1534, 53.7854) to (7.1534, 57.7854)
  arc A9 centre (7.1534, 61.7854) radius 4 clockwise from (11.1534, 61.7854) to (7.1534, 57.7854)
  arc A10 centre (15.1534, 61.7854) radius 4 clockwise from (11.1534, 61.7854) to (15.1534, 65.7854)
  arc A11 centre (6.7534, 62.1854) radius 6 clockwise from (0.7534, 62.1854) to (6.7534, 68.1854)
  arc A12 centre (6.7534, -16.6146) radius 6 clockwise from (6.7534, -22.6146) to (0.7534, -16.6146)
  arc A13 centre (7.1534, -8.2146) radius 4 clockwise from (7.1534, -12.2146) to (3.1534, -8.2146)
  arc A14 centre (7.1534, -16.2146) radius 4 clockwise from (7.1534, -12.2146) to (11.1534, -16.2146)
  arc A15 centre (15.1534, -16.2146) radius 4 clockwise from (15.1534, -20.2146) to (11.1534, -16.2146)
  arc A16 centre (71.1534, -16.2146) radius 4 clockwise from (75.1534, -16.2146) to (71.1534, -20.2146)
  arc A17 centre (79.1534, -16.2146) radius 4 clockwise from (75.1534, -16.2146) to (79.1534, -12.2146)
  arc A18 centre (79.1534, -8.2146) radius 4 clockwise from (83.1534, -8.2146) to (79.1534, -12.2146)
  point P38 (85.5534, 22.7854)
  point P39 (0.7534, 22.7854)
  point P12 (71.1534, 65.7854)
  point P49 (71.1534, -20.2146)
  point P13 (75.1534, 61.7854)
  point P48 (75.1534, -16.2146)
  point P15 (79.1534, 57.7854)
  point P51 (79.1534, -12.2146)
  point P16 (83.1534, 53.7854)
  point P53 (83.1534, -8.2146)
  point P24 (3.1534, 53.7854)
  point P42 (3.1534, -8.2146)
  point P25 (7.1534, 57.7854)
  point P41 (7.1534, -12.2146)
  point P27 (11.1534, 61.7854)
  point P44 (11.1534, -16.2146)
  point P28 (15.1534, 65.7854)
  point P46 (15.1534, -20.2146)
  midpoint L1 P38
  midpoint L11 P39
  symmetric P12 L13 P49
  symmetric P13 L13 P48
  symmetric A3 L13 A16
  symmetric P15 L13 P51
  symmetric A4 L13 A17
  symmetric P16 L13 P53
  symmetric A5 L13 A18
  symmetric P24 L13 P42
  symmetric P25 L13 P41
  symmetric A8 L13 A13
  symmetric P27 L13 P44
  symmetric A9 L13 A14
  symmetric P28 L13 P46
  symmetric A10 L13 A15
extrude "Estrusione10" add sketch "Schizzo10" profile of L5 A6 L6 A7 L7 A13 A14 A15 A16 A17 A18 against normal blind 20
extrude "Estrusione11" cut of existing geometry blind -11.284
sketch "Schizzo11" plane through (0, 25.4136, 0) normal (0, 1, 0) x axis (-1, 0, 0)
  line L1 (85.5534, 62.1854) -> (85.5534, -16.6146)
  line L2 (50.6534, 68.1854) -> (79.5534, 68.1854)
  line L3 (50.6534, 65.7854) -> (50.6534, 68.1854)
  line L4 (71.1534, 65.7854) -> (50.6534, 65.7854)
  line L5 (83.1534, -8.2146) -> (83.1534, 53.7854)
  line L6 (15.1534, -20.2146) -> (71.1534, -20.2146)
  line L7 (3.1534, 53.7854) -> (3.1534, -8.2146)
  line L8 (35.6534, 65.7854) -> (15.1534, 65.7854)
  line L9 (35.6534, 68.1854) -> (35.6534, 65.7854)
  line L10 (6.7534, 68.1854) -> (35.6534, 68.1854)
  line L11 (0.7534, -16.6146) -> (0.7534, 62.1854)
  line L12 (79.5534, -22.6146) -> (6.7534, -22.6146)
  circle C1 centre (79.1534, 61.7854) radius 1.875
  circle C2 centre (7.1534, 61.7854) radius 1.875
  arc A1 centre (79.5534, -16.6146) radius 6 clockwise from (85.5534, -16.6146) to (79.5534, -22.6146)
  arc A2 centre (79.5534, 62.1854) radius 6 clockwise from (79.5534, 68.1854) to (85.5534, 62.1854)
  arc A3 centre (71.1534, 61.7854) radius 4 clockwise from (71.1534, 65.7854) to (75.1534, 61.7854)
  arc A4 centre (79.1534, 61.7854) radius 4 clockwise from (79.1534, 57.7854) to (75.1534, 61.7854)
  arc A5 centre (79.1534, 53.7854) radius 4 clockwise from (79.1534, 57.7854) to (83.1534, 53.7854)
  arc A6 centre (79.1534, -8.2146) radius 4 clockwise from (83.1534, -8.2146) to (79.1534, -12.2146)
  arc A7 centre (79.1534, -16.2146) radius 4 clockwise from (75.1534, -16.2146) to (79.1534, -12.2146)
  arc A8 centre (71.1534, -16.2146) radius 4 clockwise from (75.1534, -16.2146) to (71.1534, -20.2146)
  arc A9 centre (15.1534, -16.2146) radius 4 clockwise from (15.1534, -20.2146) to (11.1534, -16.2146)
  arc A10 centre (7.1534, -16.2146) radius 4 clockwise from (7.1534, -12.2146) to (11.1534, -16.2146)
  arc A11 centre (7.1534, -8.2146) radius 4 clockwise from (7.1534, -12.2146) to (3.1534, -8.2146)
  arc A12 centre (7.1534, 53.7854) radius 4 clockwise from (3.1534, 53.7854) to (7.1534, 57.7854)
  arc A13 centre (7.1534, 61.7854) radius 4 clockwise from (11.1534, 61.7854) to (7.1534, 57.7854)
  arc A14 centre (15.1534, 61.7854) radius 4 clockwise from (11.1534, 61.7854) to (15.1534, 65.7854)
  arc A15 centre (6.7534, 62.1854) radius 6 clockwise from (0.7534, 62.1854) to (6.7534, 68.1854)
  arc A16 centre (6.7534, -16.6146) radius 6 clockwise from (6.7534, -22.6146) to (0.7534, -16.6146)
  arc A17 centre (7.1534, -16.2146) radius 4 clockwise from (7.1534, -12.2146) to (11.1534, -16.2146)
  arc A18 centre (79.1534, -16.2146) radius 4 clockwise from (75.1534, -16.2146) to (79.1534, -12.2146)
  circle C3 centre (7.1534, -16.2146) radius 1.725
  circle C4 centre (79.1534, -16.2146) radius 1.725
extrude "Estrusione12" cut sketch "Schizzo11" profile of C3 C4 against normal blind 1580.295
sketch "Schizzo12" plane through (0, 0, 68.1854) normal (0, 0, 1) x axis (-1, 0, 0)
  line L1 (6.7534, -5.4136) -> (35.6534, -5.4136)
  line L2 (6.7534, -25.4136) -> (6.7534, -5.4136)
  line L3 (35.6534, -25.4136) -> (6.7534, -25.4136)
  line L4 (35.6534, -5.4136) -> (35.6534, -25.4136)
  line L5 (49.6534, -7.4136) -> (36.6534, -7.4136)
  line L6 (50.6534, -5.4136) -> (50.6534, -6.4136)
  line L7 (36.6534, -4.4136) -> (49.6534, -4.4136)
  line L8 (35.6534, -6.4136) -> (35.6534, -5.4136)
  line L9 (50.6534, -5.4136) -> (79.5534, -5.4136)
  line L10 (50.6534, -25.4136) -> (50.6534, -5.4136)
  line L11 (79.5534, -25.4136) -> (50.6534, -25.4136)
  line L12 (79.5534, -5.4136) -> (79.5534, -25.4136)
  line L13 (35.6534, -25.4136) -> (50.6534, -25.4136)
  circle C1 centre (48.6534, -5.9136) radius 1.25
  circle C2 centre (37.6534, -5.9136) radius 1.25
  arc A1 centre (36.6534, -6.4136) radius 1 clockwise from (36.6534, -7.4136) to (35.6534, -6.4136)
  arc A2 centre (49.6534, -6.4136) radius 1 clockwise from (50.6534, -6.4136) to (49.6534, -7.4136)
  arc A3 centre (49.6534, -5.4136) radius 1 clockwise from (49.6534, -4.4136) to (50.6534, -5.4136)
  arc A4 centre (36.6534, -5.4136) radius 1 clockwise from (35.6534, -5.4136) to (36.6534, -4.4136)
  point P22 (50.6534, -25.4136)
  point P24 (50.6534, -25.4136)
  point P5 (35.6534, -25.4136)
  point P25 (35.6534, -25.4136)
  coincident P22 P24
  coincident P5 P25
extrude "Estrusione13" add sketch "Schizzo12" profile of L4 A1 L5 A2 L10 L13 against normal blind 2.4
